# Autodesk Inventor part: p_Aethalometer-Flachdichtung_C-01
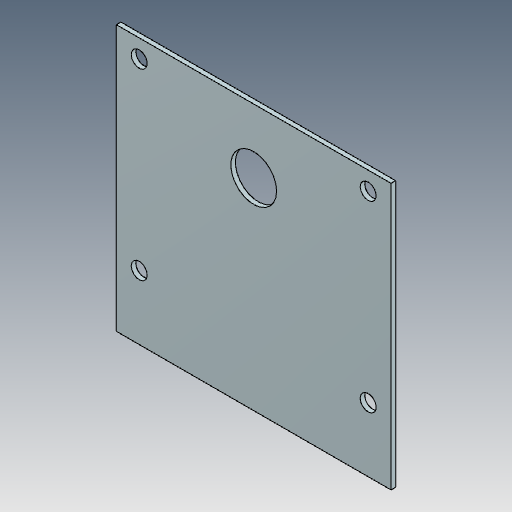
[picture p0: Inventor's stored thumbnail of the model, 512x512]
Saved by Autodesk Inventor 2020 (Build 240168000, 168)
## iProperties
Created: 2020-07
Part Number: p_Aethalometer-Flachdichtung_C-01
Material: Generisch
Document SubType Name: Modeling
Designer: Joshua Backlund
Density: 1 g/cm^3
Appearance: Vorgabe
Author: Joshua Backlund
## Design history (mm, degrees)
feature "Basis1"
feature "Basis2"
node "Volumenkörper1"
node "Volumenkörper2"
